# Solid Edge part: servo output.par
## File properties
Last saved by: nakano
Revision: 74
Density: 2712.000 kg/m^3
Accuracy: 0.990
Material: Aluminum, 6061-T6
Face Style: Aluminum
Fill Style: ANSI38(Aluminum)
Virtual Style: Polished aluminum
Grouping: Metals\Aluminium Alloys
LibraryName: Materials
Coef. of Thermal Exp: 2.3e-05
Thermal Conductivity: 180.0
Specific Heat: 920.0
Modulus of Elasticity: 68947570000.0
Poisson's Ratio: 0.33
Yield Stress: 275790280.0
Ultimate Stress: 310264065.0
Elongation: 0.0
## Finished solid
Body 1: solid body, 52 faces, 147 edges, 96 vertices.
  Faces by surface: plane 50, cylinder 1, torus 1
  Edges by curve: line 96, intersection 48, circle 3
Bounding box of the edges (mm; curved faces can reach further): 5.690 x 3.912 x 5.690, from (-2.8448, 0, -2.8448) to (2.8448, 3.9116, 2.8448).
Cylindrical faces by radius (mm): R1.5 x1
Toroidal faces (ring radius, tube radius in mm): R2.4638 r0.381 x1
Planar faces by outward normal: +x 2, +y 1, +z 2, -x 2, -y 1, -z 2, oblique 40
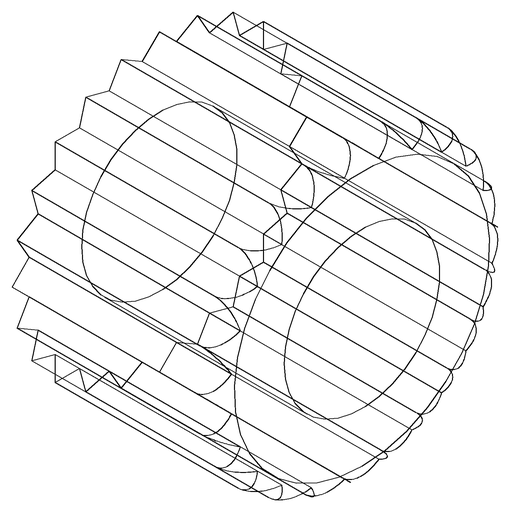
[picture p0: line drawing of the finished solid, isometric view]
